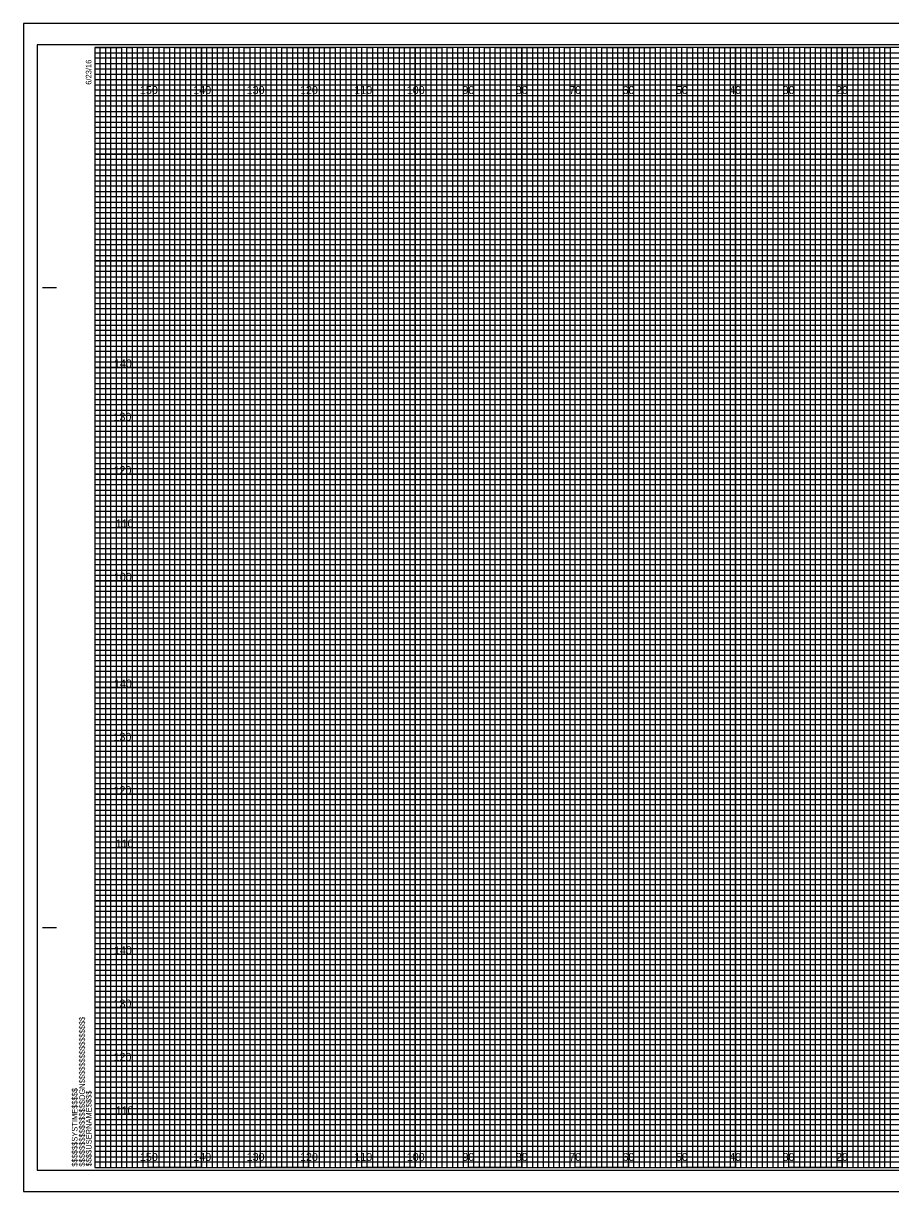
# Model space of a CAD drawing. Extents: x -13 to 323, y -5 to 1974.
# Drawn here: x -13.4 to 149.1, y 215.5 to 434.5 of the extents above; entities that cross this region are included whole.
import ezdxf

# ---------------------------------------------------------------- set-up
doc = ezdxf.new("R2010")
doc.units = 0
for name, color, linetype in [('Exist Cross Section Cell', 7, 'Continuous'), ('Exist XS Center Line Elevation Label', 7, 'Continuous'), ('Exist XS Ground Line', 7, 'Continuous'), ('Prop CMT Pvmt Course 1', 7, 'Continuous'), ('Prop CMT Pvmt Course 3', 7, 'Continuous'), ('Prop CMT Pvmt Surface', 7, 'Continuous'), ('Prop CMT Pvmt Surface Shoulder', 7, 'Continuous'), ('Prop CMT Shld Paved Course 1', 7, 'Continuous'), ('Prop CMT Shld Paved Course 2', 7, 'Continuous'), ('Prop CMT Shld Paved Course 3', 7, 'Continuous'), ('Prop CMT Subgrade Earthwork', 7, 'Continuous')]:
    doc.layers.add(name, color=color, linetype=linetype)

msp = doc.modelspace()

# ---------------------------------------------------------------- linework, layer by layer
at = {"layer": 'Exist XS Center Line Elevation Label'}
for points in [[(0, 430), (5, 430), (5, 220), (15, 220), (15, 430), (25, 430), (25, 220), (35, 220), (35, 430), (45, 430), (45, 220), (55, 220), (55, 430), (65, 430), (65, 220), (75, 220), (75, 430), (85, 430), (85, 220), (95, 220), (95, 430), (105, 430), (105, 220), (115, 220), (115, 430), (125, 430), (125, 220), (135, 220), (135, 430), (145, 430), (145, 220), (155, 220)], [(0, 425), (275, 425)], [(0, 405), (320, 405), (320, 415), (0, 415)], [(0, 385), (320, 385), (320, 395), (0, 395)], [(0, 365), (320, 365), (320, 375), (0, 375)], [(0, 345), (320, 345), (320, 355), (0, 355)], [(0, 325), (320, 325), (320, 335), (0, 335)], [(0, 305), (320, 305), (320, 315), (0, 315)], [(0, 285), (320, 285), (320, 295), (0, 295)], [(0, 265), (320, 265), (320, 275), (0, 275)], [(0, 245), (320, 245), (320, 255), (0, 255)], [(0, 225), (320, 225), (320, 235), (0, 235)]]:
    msp.add_lwpolyline(points, dxfattribs=at)
at = {"layer": 'Exist XS Ground Line'}
for p, q in [((10, 430), (0, 430)), ((10, 220), (10, 430)), ((30, 430), (20, 430)), ((20, 430), (20, 220)), ((30, 220), (30, 430)), ((50, 430), (40, 430)), ((40, 430), (40, 220)), ((50, 220), (50, 430)), ((70, 430), (60, 430)), ((60, 430), (60, 220)), ((70, 220), (70, 430)), ((90, 430), (80, 430)), ((80, 430), (80, 220)), ((90, 220), (90, 430)), ((110, 430), (100, 430)), ((100, 430), (100, 220)), ((110, 220), (110, 430)), ((130, 430), (120, 430)), ((120, 430), (120, 220)), ((130, 220), (130, 430)), ((150, 430), (140, 430)), ((140, 430), (140, 220)), ((20, 220), (10, 220)), ((40, 220), (30, 220)), ((60, 220), (50, 220)), ((80, 220), (70, 220)), ((100, 220), (90, 220)), ((120, 220), (110, 220)), ((140, 220), (130, 220))]:
    msp.add_line(p, q, dxfattribs=at)
for points in [[(0, 420), (320, 420), (320, 410), (0, 410)], [(0, 400), (320, 400), (320, 390), (0, 390)], [(0, 380), (320, 380), (320, 370), (0, 370)], [(0, 360), (320, 360), (320, 350), (0, 350)], [(0, 340), (320, 340), (320, 330), (0, 330)], [(0, 320), (320, 320), (320, 310), (0, 310)], [(0, 300), (320, 300), (320, 290), (0, 290)], [(0, 280), (320, 280), (320, 270), (0, 270)], [(0, 260), (320, 260), (320, 250), (0, 250)], [(0, 240), (320, 240), (320, 230), (0, 230)]]:
    msp.add_lwpolyline(points, dxfattribs=at)
at = {"layer": 'Prop CMT Pvmt Course 3'}
msp.add_lwpolyline([(-13.4, 215.5), (323.3, 215.5), (323.3, 434.5), (-13.4, 434.5)], close=True, dxfattribs=at)
at = {"layer": 'Prop CMT Pvmt Surface'}
for p, q in [((10, 220), (10, 430)), ((20, 220), (20, 430)), ((30, 220), (30, 430)), ((40, 220), (40, 430)), ((50, 220), (50, 430)), ((60, 220), (60, 430)), ((70, 220), (70, 430)), ((80, 220), (80, 430)), ((90, 220), (90, 430)), ((100, 220), (100, 430)), ((110, 220), (110, 430)), ((120, 220), (120, 430)), ((130, 220), (130, 430)), ((140, 220), (140, 430)), ((0, 420), (320, 420)), ((0, 410), (320, 410)), ((0, 400), (320, 400)), ((0, 390), (320, 390)), ((0, 380), (320, 380)), ((0, 370), (320, 370)), ((0, 360), (320, 360)), ((0, 350), (320, 350)), ((0, 340), (320, 340)), ((0, 330), (320, 330)), ((0, 320), (320, 320)), ((0, 310), (320, 310)), ((0, 300), (320, 300)), ((0, 290), (320, 290)), ((0, 280), (320, 280)), ((0, 270), (320, 270)), ((0, 260), (320, 260)), ((0, 250), (320, 250)), ((0, 240), (320, 240)), ((0, 230), (320, 230))]:
    msp.add_line(p, q, dxfattribs=at)
at = {"layer": 'Prop CMT Pvmt Surface Shoulder'}
for p, q in [((323.3, 434.5), (-13.4, 434.5)), ((-13.4, 434.5), (-13.4, 215.5)), ((-13.4, 215.5), (323.3, 215.5))]:
    msp.add_line(p, q, dxfattribs=at)
at = {"layer": 'Prop CMT Shld Paved Course 1'}
for p, q in [((0, 429), (260, 429)), ((260, 427.98), (0, 427.98)), ((0, 427.98), (0, 427)), ((0, 427), (260, 427)), ((260, 425.89), (0, 425.89)), ((0, 425.89), (0, 424)), ((0, 424), (320, 424))]:
    msp.add_line(p, q, dxfattribs=at)
for points in [[(0, 423), (270, 423), (320, 423), (320, 422), (0, 422)], [(0, 421), (320, 421), (320, 419), (0, 419)], [(0, 418), (320, 418), (320, 417), (0, 416.98)], [(0, 416), (320, 416), (320, 414), (0, 414)], [(0, 413), (320, 413), (320, 412), (0, 412)], [(0, 411), (320, 411), (320, 409), (0, 409)], [(0, 408), (320, 408), (320, 407), (0, 407)], [(0, 406), (320, 406), (320, 404), (0, 404)], [(0, 403), (320, 403), (320, 402), (0, 402)], [(0, 401), (320, 401), (320, 399), (0, 399)], [(0, 398), (320, 398), (320, 397), (0, 397)], [(0, 396), (320, 396), (320, 393.95), (320, 393), (320, 392), (0, 392)], [(0, 394), (320, 394), (320, 393), (0, 393)], [(0, 391), (320, 391), (320, 389), (0, 389.03)], [(0, 389.03), (320, 389), (320, 388), (0, 388)], [(0, 387), (320, 387), (320, 386), (0, 386)], [(0, 384), (320, 384), (320, 383), (0, 383)], [(0, 382), (320, 382), (320, 381), (0, 381)], [(-0.07, 378.89), (320, 378.89), (320, 377.88), (-0.07, 377.88)], [(0, 377), (320, 377), (320, 376), (0, 376)], [(0, 374), (320, 374), (320, 373), (0, 373)], [(0, 372), (320, 372), (320, 371), (0, 371)], [(0, 369), (320, 369), (320, 368), (0, 368)], [(0, 367), (320, 367), (320, 366), (0, 366)], [(0, 364), (320, 364), (320, 363), (0, 363)], [(0, 362), (320, 362), (320, 361), (0, 361)], [(0, 359), (320, 359), (319.99, 357.98), (0, 358)], [(0, 357), (320, 357), (320, 356), (0, 356)], [(0, 354), (320, 354), (320, 353), (0, 353)], [(0, 352), (320, 352), (320, 351), (0, 351)], [(0, 349), (320, 349), (320, 348), (0, 348)], [(0, 347), (320, 347), (320, 346), (0, 346)], [(0, 344), (320, 344), (320, 343), (0, 343)], [(0, 342), (320, 342), (320, 341), (0, 341)], [(0, 339), (320, 339), (320, 338), (0, 338)], [(0, 336.99), (320.07, 336.91), (320, 336), (0, 336)], [(0, 334), (320, 334), (320, 333), (0, 333)], [(0, 332), (320, 332), (320, 331), (0, 331)], [(0, 329), (320, 329), (320, 328), (0, 328)], [(0, 327), (320, 327), (320, 326), (0, 326)], [(0, 324), (320, 324), (320, 323), (0, 323)], [(0, 322), (320, 322), (320, 321), (0, 321)], [(0, 319), (320, 319), (320, 318), (0, 318)], [(0, 317), (320, 317), (320, 316), (0, 316)], [(0, 314), (320, 314), (320, 313), (0, 313)], [(0, 312), (320, 312), (320, 311), (0, 311)], [(0, 309), (320, 309), (320, 308), (0, 308)], [(0, 307), (320, 307), (320, 306), (0, 306)], [(0, 304), (320, 304), (320, 303), (0, 303)], [(0, 302), (320, 302), (320, 301), (0, 301)], [(0, 299), (320, 299), (319.99, 297.98), (0, 298)], [(0, 297), (320, 297), (320, 296), (0, 296)], [(0, 294), (320, 294), (320, 293), (0, 293)], [(0, 292), (320, 292), (320, 291), (0, 291)], [(0, 289), (320, 289), (320, 288), (0, 288)], [(0, 287), (320, 287), (320, 286), (0, 286)], [(0, 284), (320, 284), (320, 283), (0, 283)], [(0, 282), (320, 282), (320, 281), (0, 281)], [(0, 279), (320, 279), (320, 278), (0, 278)], [(0, 276.99), (320.07, 276.91), (320, 276), (0, 276)], [(0, 274), (320, 274), (320, 273), (0, 273)], [(0, 272), (320, 272), (320, 271), (0, 271)], [(0, 269), (320, 269), (320, 268), (0, 268)], [(0, 267), (320, 267), (320, 266), (0, 266)], [(0, 264), (320, 264), (320, 263), (0, 263)], [(0, 262), (320, 262), (320, 261), (0, 261)], [(0, 259), (320, 259), (320, 258), (0, 258)], [(0, 257), (320, 257), (320, 256), (0, 256)], [(0, 254), (320, 254), (320, 253), (0, 253)], [(0, 252), (320, 252), (320, 251), (0, 251)], [(0, 249), (320, 249), (320, 248), (0, 248)], [(0, 247), (320, 247), (320, 246), (0, 246)], [(0, 244), (320, 244), (320, 243), (0, 243)], [(0, 242), (320, 242), (320, 241), (0, 241)], [(0, 239), (320, 239), (320, 238), (0, 238)], [(0, 237), (320, 237), (320, 236), (0, 236)], [(0, 234), (320, 234), (320, 233), (0, 233)], [(0, 232), (320, 232), (320, 231), (0, 231)], [(0, 229), (320, 229), (320, 228), (0, 228)], [(0, 227), (320, 227), (320, 226), (0, 226)], [(0, 224), (320, 224), (320, 223), (0, 223)], [(0, 222), (320, 222), (320, 221), (0, 221)]]:
    msp.add_lwpolyline(points, dxfattribs=at)
at = {"layer": 'Prop CMT Shld Paved Course 2'}
for p, q in [((-9.8, 385), (-7.3, 385)), ((-9.7, 385), (-7.2, 385)), ((-9.8, 265), (-7.3, 265)), ((-9.7, 265), (-7.2, 265)), ((0, 220), (0, 220)), ((0, 220), (0, 220)), ((0, 220), (0, 220)), ((0, 220), (0, 220)), ((0, 220), (0, 220)), ((0, 220), (0, 220)), ((0, 220), (0, 220))]:
    msp.add_line(p, q, dxfattribs=at)
msp.add_lwpolyline([(320, 430), (0, 430), (0, 220), (320, 220)], close=True, dxfattribs=at)
at = {"layer": 'Prop CMT Shld Paved Course 3'}
for points in [[(0, 220), (1, 220), (1, 430), (2, 430), (2, 220)], [(2, 220), (3, 220), (3, 430), (4, 430), (4, 220)], [(5, 220), (6, 220), (6, 430), (7, 430), (7, 220)], [(7, 220), (8, 220), (8, 430), (9, 430), (9, 220)], [(10, 220), (11, 220), (11, 430), (12, 430), (12, 220)], [(12, 220), (13, 220), (13, 430), (14, 430), (14, 220)], [(15, 220), (16, 220), (16, 430), (17, 430), (17, 220)], [(17, 220), (18, 220), (18, 430), (19, 430), (19, 220)], [(20, 220), (21, 220), (21, 430), (22, 430), (22, 220)], [(22, 220), (23, 220), (23, 430), (24, 430), (24, 220)], [(25, 220), (26, 220), (26, 430), (27, 430), (27, 220)], [(27, 220), (28, 220), (28, 430), (29, 430), (29, 220)], [(30, 220), (31, 220), (31, 430), (32, 430), (32, 220)], [(32, 220), (33, 220), (33, 430), (34, 430), (34, 220)], [(35, 220), (36, 220), (36, 430), (37, 430), (37, 220)], [(37, 220), (38, 220), (38, 430), (39, 430), (39, 220)], [(40, 220), (41, 220), (41, 430), (42, 430), (42, 220)], [(42, 220), (43, 220), (43, 430), (44, 430), (44, 220)], [(45, 220), (46, 220), (46, 430), (47, 430), (47, 220)], [(47, 220), (48, 220), (48, 430), (49, 430), (49, 220)], [(50, 220), (51, 220), (51, 430), (52, 430), (52, 220)], [(52, 220), (53, 220), (53, 430), (54, 430), (54, 220)], [(55, 220), (56, 220), (56, 430), (57, 430), (57, 220)], [(57, 220), (58, 220), (58, 430), (59, 430), (59, 220)], [(60, 220), (61, 220), (61, 430), (62, 430), (62, 220)], [(62, 220), (63, 220), (63, 430), (64, 430), (64, 220)], [(65, 220), (66, 220), (66, 430), (67, 430), (67, 220)], [(67, 220), (68, 220), (68, 430), (69, 430), (69, 220)], [(70, 220), (71, 220), (71, 430), (72, 430), (72, 220)], [(72, 220), (73, 220), (73, 430), (74, 430), (74, 220)], [(75, 220), (76, 220), (76, 430), (77, 430), (77, 220)], [(77, 220), (78, 220), (78, 430), (79, 430), (79, 220)], [(80, 220), (81, 220), (81, 430), (82, 430), (82, 220)], [(82, 220), (83, 220), (83, 430), (84, 430), (84, 220)], [(85, 220), (86, 220), (86, 430), (87, 430), (87, 220)], [(87, 220), (88, 220), (88, 430), (89, 430), (89, 220)], [(90, 220), (91, 220), (91, 430), (92, 430), (92, 220)], [(92, 220), (93, 220), (93, 430), (94, 430), (94, 220)], [(95, 220), (96, 220), (96, 430), (97, 430), (97, 220)], [(97, 220), (98, 220), (98, 430), (99, 430), (99, 220)], [(100, 220), (101, 220), (101, 430), (102, 430), (102, 220)], [(102, 220), (103, 220), (103, 430), (104, 430), (104, 220)], [(105, 220), (106, 220), (106, 430), (107, 430), (107, 220)], [(107, 220), (108, 220), (108, 430), (109, 430), (109, 220)], [(110, 220), (111, 220), (111, 430), (112, 430), (112, 220)], [(112, 220), (113, 220), (113, 430), (114, 430), (114, 220)], [(115, 220), (116, 220), (116, 430), (117, 430), (117, 220)], [(117, 220), (118, 220), (118, 430), (119, 430), (119, 220)], [(120, 220), (121, 220), (121, 430), (122, 430), (122, 220)], [(122, 220), (123, 220), (123, 430), (124, 430), (124, 220)], [(125, 220), (126, 220), (126, 430), (127, 430), (127, 220)], [(127, 220), (128, 220), (128, 430), (129, 430), (129, 220)], [(130, 220), (131, 220), (131, 430), (132, 430), (132, 220)], [(132, 220), (133, 220), (133, 430), (134, 430), (134, 220)], [(135, 220), (136, 220), (136, 430), (137, 430), (137, 220)], [(137, 220), (138, 220), (138, 430), (139, 430), (139, 220)], [(140, 220), (141, 220), (141, 430), (142, 430), (142, 220)], [(142, 220), (143, 220), (143, 430), (144, 430), (144, 220)], [(145, 220), (146, 220), (146, 430), (147, 430), (147, 220)], [(147, 220), (148, 220), (148, 430), (149, 430), (149, 220)]]:
    msp.add_lwpolyline(points, dxfattribs=at)
at = {"layer": 'Prop CMT Subgrade Earthwork'}
msp.add_lwpolyline([(-10.8, 219.5), (322.4, 219.5), (322.4, 430.5), (-10.8, 430.5)], close=True, dxfattribs=at)

# ---------------------------------------------------------------- texts
at = {"layer": 'Exist Cross Section Cell'}
for s, p in [('150', (8.44, 421.25)), ('140', (18.44, 421.25)), ('130', (28.44, 421.25)), ('120', (38.44, 421.25)), ('110', (48.62, 421.25)), ('100', (58.44, 421.25)), ('90', (68.86, 421.25)), ('80', (78.86, 421.25)), ('70', (88.86, 421.25)), ('60', (98.86, 421.25)), ('50', (108.86, 421.25)), ('40', (118.86, 421.25)), ('30', (128.86, 421.25)), ('20', (138.86, 421.25)), ('150', (8.44, 221.25)), ('140', (18.44, 221.25)), ('130', (28.44, 221.25)), ('120', (38.44, 221.25)), ('110', (48.62, 221.25)), ('100', (58.44, 221.25)), ('90', (68.86, 221.25)), ('80', (78.86, 221.25)), ('70', (88.86, 221.25)), ('60', (98.86, 221.25)), ('50', (108.86, 221.25)), ('40', (118.86, 221.25)), ('30', (128.86, 221.25)), ('20', (138.86, 221.25))]:
    msp.add_text(s, height=1.5, dxfattribs=at).set_placement(p)
at = {"layer": 'Prop CMT Pvmt Course 1'}
for s, p in [('140', (3.57, 370)), ('130', (3.49, 360)), ('120', (3.5, 350)), ('110', (3.88, 340)), ('100', (3.55, 330)), ('140', (3.57, 310)), ('130', (3.49, 300)), ('120', (3.5, 290)), ('110', (3.88, 280)), ('140', (3.57, 260)), ('130', (3.49, 250)), ('120', (3.5, 240)), ('110', (3.88, 230))]:
    msp.add_text(s, height=1.5, dxfattribs=at).set_placement(p)
at = {"layer": 'Prop CMT Shld Paved Course 2'}
for s, p in [('6/23/16', (-0.65, 423)), ('$$$$$$$$$$$$$$$$DGN$$$$$$$$$$$$$$$$', (-1.88, 220.18)), ('$$$$$$SYSTIME$$$$$', (-3.26, 220.18)), ('$$$$USERNAME$$$$', (-0.62, 220.23))]:
    msp.add_text(s, height=1.05, rotation=90, dxfattribs=at).set_placement(p)

doc.saveas('drawing.dxf')
